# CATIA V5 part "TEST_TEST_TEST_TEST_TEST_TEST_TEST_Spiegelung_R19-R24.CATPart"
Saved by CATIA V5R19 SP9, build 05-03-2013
Part number: Part_zum_spiegeln
Bounding box of the stored display mesh (mm): x -32.796 to 15.753, y -87.959 to 0, z 0 to 40
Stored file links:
  L:\pool\2209\09_Prüfungen-Kinematik-Gewicht\TEST_TEST_TEST_TEST_TEST_TEST_TEST_Spiegelung_R19-R24.CATPart
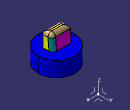
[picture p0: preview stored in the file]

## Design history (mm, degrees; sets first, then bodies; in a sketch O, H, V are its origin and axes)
AxisSystem1: origin (0, 0, 0), X (1, 0, 0), Y (0, 1, 0), Z (0, 0, 1)
Body1 (main body)
  Body2
    Sketch1 on XY plane of AxisSystem1, origin (0, 0, 0), H (1, 0, 0), V (0, 1, 0)
      circle A1 centre (-8.5216, -63.6867) radius 24.2744
    Pad1: profile Sketch1, direction (0, 0, 1), length 20
    Sketch2 on end face of Pad1, origin (0, 0, 20), H (1, 0, 0), V (0, 1, 0)
      line L1 (3.5198, -70.3364) -> (-21.2085, -70.3364)
      line L2 (-21.2085, -70.3364) -> (-21.2085, -56.5388)
      line L3 (-21.2085, -56.5388) -> (3.5198, -56.5388)
      line L4 (3.5198, -56.5388) -> (3.5198, -70.3364)
      horizontal: L1 H, L3 H
      vertical: L2 V, L4 V
    Pad2: profile Sketch2, direction (0, 0, 1), length 20
    Draft1: PullDir end face of Pad1, Angle 5, SupportToDraft face of Pad2 from Sketch2.L3, Neutral end face of Pad1
    Fillet1: radius 5, on edge [face of Pad2 from Sketch2.L3 | face of Pad2 from Sketch2.L4]
    Chamfer1: length 1, angle 45, on edge [face of Pad2 from Sketch2.L4 | face of Pad2 from Sketch2.L1]
    Fillet2: radius 5, on end face of Pad2
  Assemble1: tool Body2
